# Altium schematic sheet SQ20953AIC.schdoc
size 127 x 101 mm
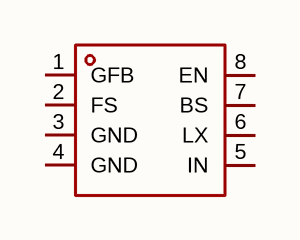
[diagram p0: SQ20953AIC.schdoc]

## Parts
U?  sq20953aic  [TSOT-23-8_L2.9-W1.6-P0.65-LS2.8-BR]  (value not drawn)

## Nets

Not connected (* = marked no-connect by the designer): U? 1(GFB) 2(FS) 3(GND) 4(GND) 5(IN) 6(LX) 7(BS) 8(EN)

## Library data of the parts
U? = sq20953aic: 功能类型:降压型;工作电压:4.5V~30V;输出电压:-;输出电流:3A;输出类型:可调;; Manufacturer: Silergy(矽力杰); AddInBom: yes; ModelId: a4a866e84c1d4e21a00dbb6d6e7ebbb6; ModelTransform: 110.45568,114.173,0,180,0,0,0,0,0; Function: 降压型; Output Current: 3A; Frequency - Switching: 500kHz~2.5MHz; Synchronous Rectifier: 是; Number of Outputs: 1; Topology: 降压式; Quiescent Current: 10uA; Switch tube (built-in/external): 内置; Output Type: 可调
